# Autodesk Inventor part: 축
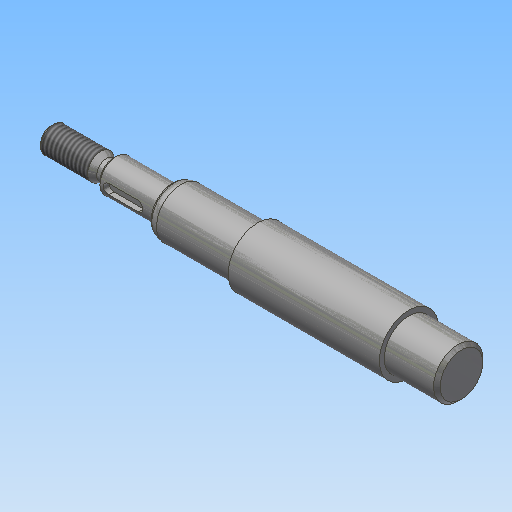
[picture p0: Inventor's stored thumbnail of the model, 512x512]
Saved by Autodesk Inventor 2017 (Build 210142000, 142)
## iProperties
Created: 2015-11
Part Number: 축
Material: 강철, 연강
Document SubType Name: Modeling
Designer: mduedu
Density: 1 g/cm^3
Appearance: 강철
Author: mduedu
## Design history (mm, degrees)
sketch "스케치1"
  geometry: L1 (-86, 0)-(86, 0); L2 (-86, 0)-(-86, 4); L3 (-86, 4)-(-70.732, 4); L4 (-70.732, 4)-(-69, 3); L5 (-69, 3)-(-67, 3); L6 (-67, 3)-(-67, 5); L7 (-67, 5)-(-49, 5); L8 (-49, 5)-(-49, 6.55); L9 (-47.355, 7.5)-(-23, 7.5); L10 (-23, 7.5)-(-23, 9); L11 (0, 0)-(0, 9); L12 (86, 4)-(70.732, 4); L13 (70.732, 4)-(69, 3); L14 (69, 3)-(67, 3); L15 (67, 3)-(67, 5); L16 (67, 5)-(49, 5); L17 (23, 7.5)-(23, 9); L18 (86, 0)-(86, 4); L19 (-23, 9)-(23, 9); L20 (-49, 6.55)-(-47.355, 7.5); L21 (47.355, 7.5)-(23, 7.5); L22 (49, 6.55)-(47.355, 7.5); L23 (49, 5)-(49, 6.55); 1 further point
  constraints: 46 end point, 10 symmetric about line, 6 perpendicular, 5 parallel, 2 midpoint, 1 coincident, 1 horizontal
  dimensions: "d0" = 172 distance of L1.start L1.end (derived); "d1" = 8 diameter of L3 L1; "d2" = 30 deg angle of L4 L5; "d3" = 6 diameter of L5 L1; "d4" = 10 diameter of L7 L1; "d5" = 15 diameter of L9 L1; "d6" = 18 diameter of L19 L1; "d8" = 18 distance of L6.end L7.end; "d9" = 46 distance of L10.end L17.end; "d10" = 2 distance of L4.end L5.end; "d11" = 17 distance from line of L4.end L2; "d16" = 13.1 diameter of L8.end L1; "d17" = 30 deg angle of L20 L9; "d18" = 26 distance between parallel lines of L10 L8
revolve "회전1" sketch "스케치1" stored, may be unused: angle "d12" = 90 deg
chamfer "모따기1" distance "d13" = 1; stored, may be unused: second distance "d14" = 2, angle "d15" = 45 deg
fillet "모깎기1" dims "d19" = 4, "d20" = 0.5
node "작업 평면1"
sketch "스케치2" dims "d23" = 12
  geometry: L1 (-5.5, 1.5)-(3.5, 1.5); L2 (3.5, 1.5)-(3.5, -1.5); L3 (3.5, -1.5)-(-5.5, -1.5); L4 (-5.5, -1.5)-(-5.5, 1.5); L5 (-9, -4)-(-9, 4) reference; 3 further points
  constraints: 8 end point, 2 midpoint, 2 parallel, 2 vertical alignment, 1 horizontal, 1 perpendicular, 4 other
  dimensions: "d21" = 3 distance between parallel lines of L3 L1; "d24" = 2 dimension on L5
extrude "돌출1" cut sketch "스케치2" distance "d25" = 1.8; taper "d26" = 0 deg
feature "스레드1" dims "d27" = 10, "d28" = 0
feature "스레드2" dims "d29" = 10, "d30" = 0
chamfer "모따기2" distance "d31" = 1; stored, may be unused: second distance "d32" = 2, angle "d33" = 45 deg
node "작업 평면2"
sketch "스케치3"
  geometry: C1 r 7.5 at (0, 0) reference; 1 further point
extrude "돌출2" cut sketch "스케치3" stored distance "d36" = 10; taper "d37" = 0 deg
chamfer "모따기3" distance "d38" = 1; stored, may be unused: second distance "d39" = 2, angle "d40" = 45 deg
node "솔리드1"
mirror "대칭1"
node "절단 모서리 투영1"
other parameters: "d35" = 16
